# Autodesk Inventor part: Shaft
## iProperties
Created: 2011-05
Part Number: Shaft
Material: Steel
Document SubType Name: Modeling
Designer: 904Chiaki
Density: 1 g/cm^3
CustomPartVersion: 1
Author: 904Chiaki
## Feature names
1. Revolution1
2. Chamfer3
3. Chamfer1
4. Fillet1
5. Chamfer2
